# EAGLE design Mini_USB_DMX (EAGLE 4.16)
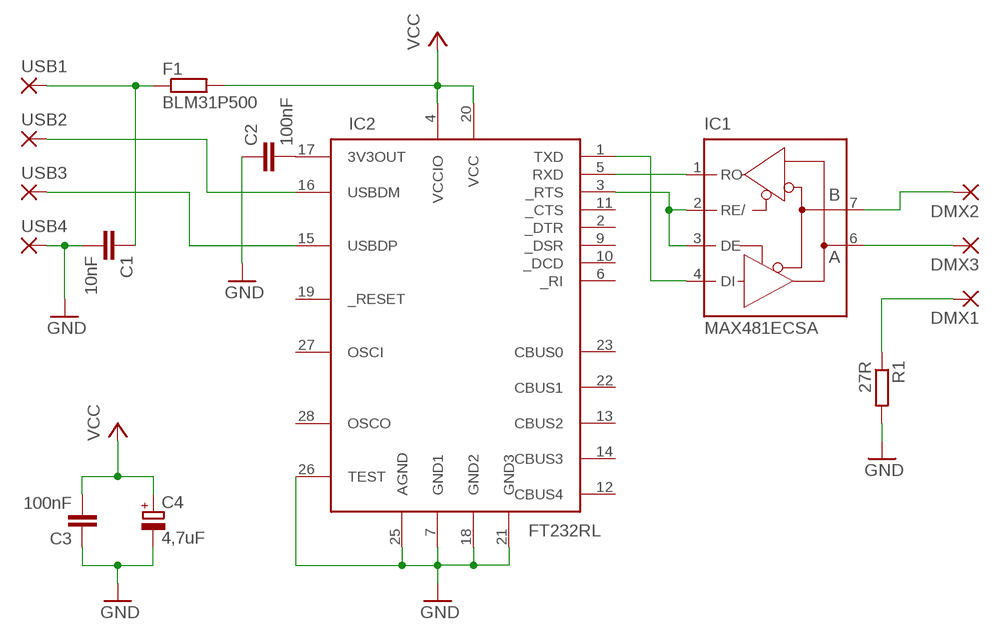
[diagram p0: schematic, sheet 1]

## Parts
C1  10nF  C-EUC2220K  [C2220K]
C2  100nF  C-EUC2220K  [C2220K]
C3  100nF  C-EUC2220K  [C2220K]
C4  4,7uF  CPOL-EU153CLV-0505  [153CLV-0505]
DMX1  2,54/0,8  [2,54/0,8]
DMX2  2,54/0,8  [2,54/0,8]
DMX3  2,54/0,8  [2,54/0,8]
F1  BLM31P500  R-EU_M1206  [M1206]
IC1  MAX481ECSA  MAX481CSA  [SO08]
IC2  FT232RL  [SSOP28DB]
R1  27R  R-EU_M1206  [M1206]
USB1  2,54/0,8  [2,54/0,8]
USB2  2,54/0,8  [2,54/0,8]
USB3  2,54/0,8  [2,54/0,8]
USB4  2,54/0,8  [2,54/0,8]

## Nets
GND: C1.2 C2.1 C3.1 C4.- IC2.7(GND1) IC2.18(GND2) IC2.21(GND3) IC2.25(AGND) IC2.26(TEST) R1.2 USB4.1(P)
N$1: IC1.2(RE/) IC1.3(DE) IC2.3(_RTS)
N$2: IC1.1(RO) IC2.5(RXD)
N$3: IC1.4(DI) IC2.1(TXD)
N$4: C1.1 F1.1 USB1.1(P)
N$5: C2.2 IC2.17(3V3OUT)
N$6: DMX3.1(P) IC1.6(A)
N$7: IC2.16(USBDM) USB2.1(P)
N$8: IC2.15(USBDP) USB3.1(P)
N$9: DMX2.1(P) IC1.7(B)
N$10: DMX1.1(P) R1.1
VCC: C3.2 C4.+ F1.2 IC2.4(VCCIO) IC2.20(VCC)
Unconnected: IC2.2(_DTR) IC2.6(_RI) IC2.9(_DSR) IC2.10(_DCD) IC2.11(_CTS) IC2.12(CBUS4) IC2.13(CBUS2) IC2.14(CBUS3) IC2.19(_RESET) IC2.22(CBUS1) IC2.23(CBUS0) IC2.27(OSCI) IC2.28(OSCO)

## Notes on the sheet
- FT232RL

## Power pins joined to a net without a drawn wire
GND: IC1.5(GND)
VCC: IC1.8(VCC)

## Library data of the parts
C1-C3 = rcl:C-EU: CAPACITOR, European symbol
C4 = rcl:CPOL-EU: POLARIZED CAPACITOR, European symbol
DMX1-DMX3 USB1-USB4 = wirepad:2,54/0,8: THROUGH-HOLE PAD
F1 R1 = rcl:R-EU_: RESISTOR, European symbol
IC1 = maxim:MAX481CSA: RS485 TRANSEIVER
IC2 = ftdichip:FT232RL: USB UART 4th Generation USB UART (USB <-> Serial) Controller

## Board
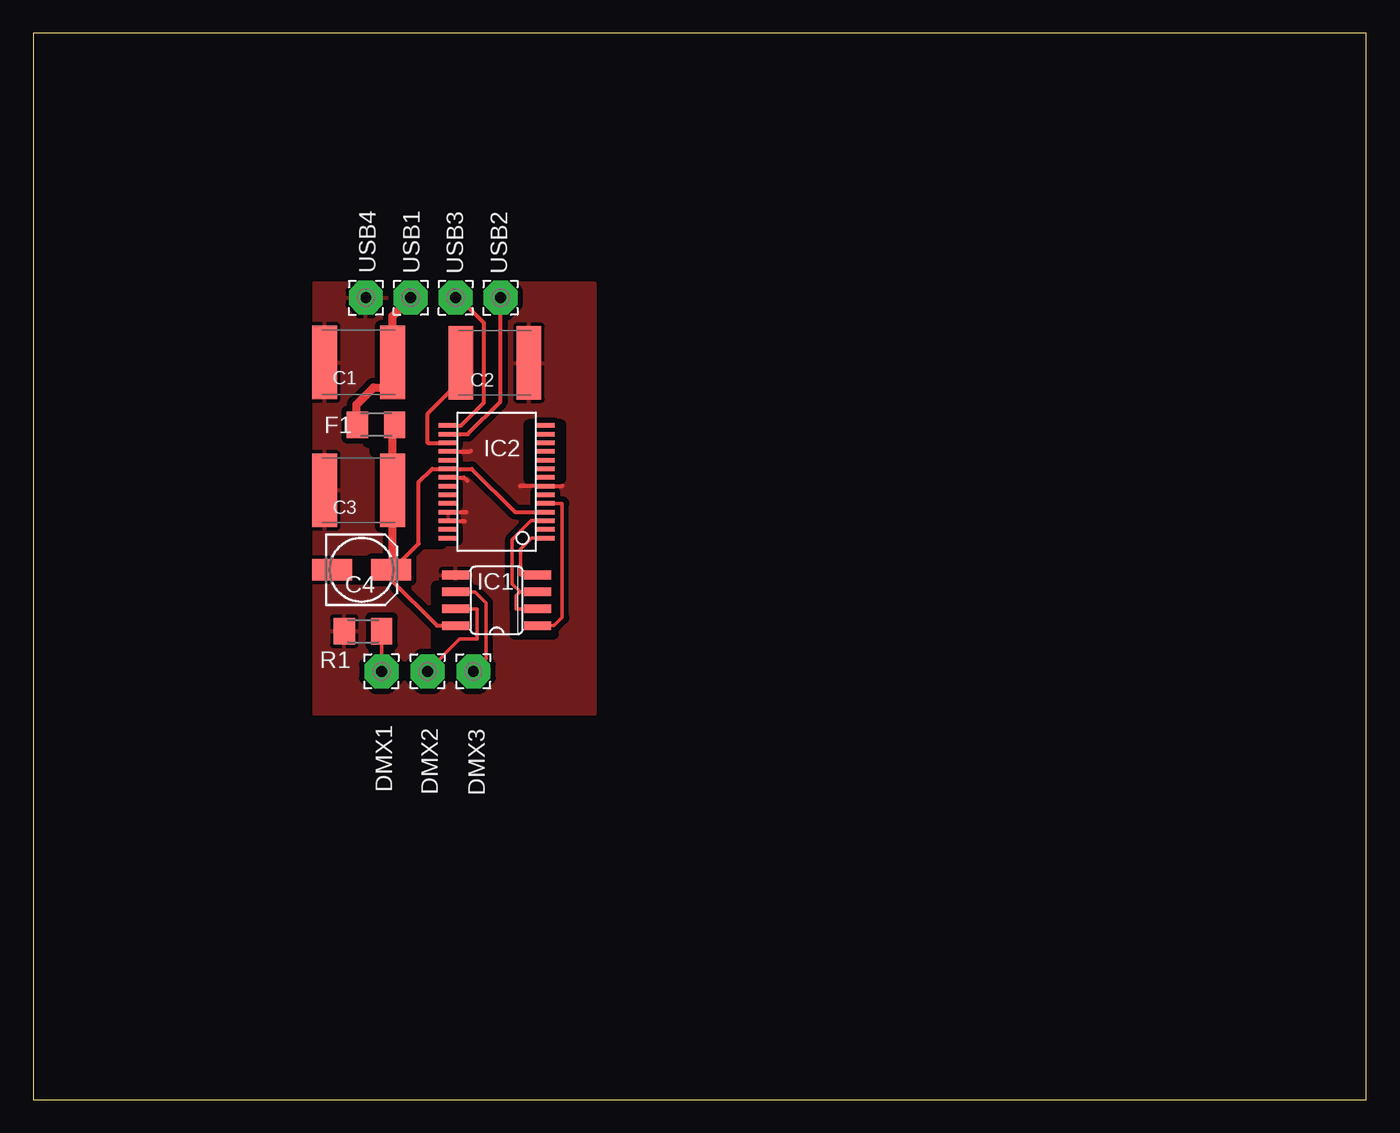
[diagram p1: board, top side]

Size 100 x 80 mm. Coordinates in mm from the lower left corner, seen from the top.
Outline: 0,0 100,0 100,80 0,80 0,0
Copper layers (1*16): Top 0.035mm / dielectric 1.5mm / Bottom 0.035mm
Design rules "default": minimum track width 10mil, minimum drill 24mil, track to track 8mil, track to pad 8mil, pad to pad 8mil, via to via 8mil, smd to smd 8mil, copper to edge 40mil, drill to drill 8mil, minimum pad ring 10mil, minimum via ring 8mil, stop-mask expansion 4mil, vias tented up to drill 0mil, thermal gap 10mil
tRestrict: area 28.9,41.7 to 30.6,50.8; area 25.1,49.3 to 26.6,52.7; area 25.6,48.6 to 26.5,49.9; area 37.2,46.6 to 39.6,50.6; area 30.2,33.6 to 31.7,38.5; area 36.1,34.9 to 39,37.8; area 23.8,39 to 25.4,40.4

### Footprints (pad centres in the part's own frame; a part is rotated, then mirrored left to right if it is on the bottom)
C2220K = smd 1.85 x 5.5: 1 -2.55,0; 2 2.55,0
153CLV-0505 = smd 3 x 1.6: + 2.2,0; - -2.2,0
2,54/0,8 = drill 0.813 pad 2.54 octagon: 1 0,0
M1206 = smd 1.6 x 2: 1 -1.4,0; 2 1.4,0
SO08 = smd 0.66 x 2.032: 1 -1.905,-3.073; 2 -0.635,-3.073; 3 0.635,-3.073; 4 1.905,-3.073; 5 1.905,3.073; 6 0.635,3.073; 7 -0.635,3.073; 8 -1.905,3.073
SSOP28DB = smd 0.348 x 1.397: 1 -4.225,-3.656; 2 -3.575,-3.656; 3 -2.925,-3.656; 4 -2.275,-3.656; 5 -1.625,-3.656; 6 -0.975,-3.656; 7 -0.325,-3.656; 8 0.325,-3.656; 9 0.975,-3.656; 10 1.625,-3.656; 11 2.275,-3.656; 12 2.925,-3.656; 13 3.575,-3.656; 14 4.225,-3.656; 15 4.225,3.656; 16 3.575,3.656; 17 2.925,3.656; 18 2.275,3.656; 19 1.625,3.656; 20 0.975,3.656; 21 0.325,3.656; 22 -0.325,3.656; 23 -0.975,3.656; 24 -1.625,3.656; 25 -2.275,3.656; 26 -2.925,3.656; 27 -3.575,3.656; 28 -4.225,3.656

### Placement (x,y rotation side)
C1  24.41,55.3 180 top
C2  34.63,55.27 180 top
C3  24.41,45.72 0 top
C4  24.63,39.75 0 top
DMX1  26.12,32.13 270 top
DMX2  29.58,32.13 270 top
DMX3  33.01,32.13 270 top
F1  25.71,50.64 0 top
IC1  34.76,37.46 90 top
IC2  34.76,46.35 90 top
R1  24.73,35.14 180 top
USB1  28.31,60.16 90 top
USB2  35.05,60.16 90 top
USB3  31.68,60.16 90 top
USB4  24.95,60.16 90 top

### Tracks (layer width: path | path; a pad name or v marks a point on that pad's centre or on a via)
GND
  Top 0.305: IC2.26 32.38,43.4 | IC2.25 32.51,44.06 | IC2.21 32.31,46.68 32.57,46.41 | IC2.18 32.78,48.62 32.82,48.67 | 39.68,46.06 39.64,46.03 IC2.7 36.54,46.03
  pour Top (isolate 0.406): 21.08,61.27 21.08,28.95 42.13,28.95 42.13,61.21
N$1
  Top 0.254: 36.54,38.1 IC1.3 | 36.54,38.1 35.94,38.7 35.94,42.03 37.33,43.43 IC2.3 | IC1.2 36.22,36.83 36.22,37.81 36.51,38.1 36.54,38.1
N$2
  Top 0.254: IC1.1 39.08,35.55 39.68,36.16 39.68,44.73 IC2.5 | IC2.5 | IC2.5
N$3
  Top 0.254: 38.44,42.1 38.44,42.12 IC2.1 | IC2.1 | IC1.4 36.54,39.37 36.54,41.3 37.36,42.13 IC2.1
N$4
  Top 0.61: 26.96,53.43 26.96,53.08 | 26.96,53.43 C1.1 26.95,55.31 26.95,58.8 USB1.1 | 24.25,50.26 24.25,50.22 | F1.1 24.25,50.26 | 24.25,50.26 24.25,52.16 25.52,53.43 26.96,53.43
N$5
  Top 0.305: IC2.17 29.58,49.28 29.58,51.46 31.58,53.46 32.06,55.21 C2.2
N$6
  Top 0.254: IC1.6 33.14,38.1 33.97,37.27 33.97,33.05 33.05,32.13 DMX3.1
N$7
  Top 0.305: IC2.16 32.59,49.93 35.05,52.38 USB2.1
N$8
  Top 0.305: IC2.15 32.09,50.58 33.81,52.29 33.81,58.26 31.9,60.16 USB3.1
N$9
  Top 0.254: IC1.7 33.3,36.83 33.3,34.54 32,34.54 DMX2.1 | DMX2.1 29.55,32.09 | DMX2.1
N$10
  Top 0.254: DMX1.1 26.12,32.09 26.13,32.09 R1.1
VCC
  Top 0.254: IC2.4 38.41,44.1
  Top 0.305: IC1.8 30.28,35.55 26.85,38.98 26.85,39.75 C4.+ 26.83,39.74 26.89,39.68 28.92,41.71 28.92,46.32 29.92,47.33 IC2.20 32.9,47.33 36.12,44.1 38.44,44.1 | 38.44,44.1 | 38.44,44.1 IC2.4
  Top 0.61: IC1.8 31.77,35.55 | F1.2 27.08,50.26 26.96,50.26 C3.2 26.96,39.71 26.83,39.71 C4.+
